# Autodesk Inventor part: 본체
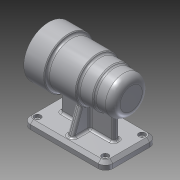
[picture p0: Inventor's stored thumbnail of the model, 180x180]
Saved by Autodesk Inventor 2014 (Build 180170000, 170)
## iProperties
Created: 2016-06
Part Number: 본체
Material: Aluminum 6061
Document SubType Name: Modeling
Designer: user
Density: 2.71 g/cm^3
Appearance: Aluminum - Flat
Mass: 673.031 g
Surface Area: 650.376 cm^2
Volume: 248.351 cm^3
Author: user
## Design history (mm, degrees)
sketch "Sketch1"
  geometry: L1 (-56, 35)-(56, 35); L2 (56, 35)-(56, -35); L3 (56, -35)-(-56, -35); L4 (-56, -35)-(-56, 35); 3 further points
  constraints: 8 end point, 2 midpoint, 2 parallel, 1 horizontal, 1 horizontal alignment, 1 perpendicular, 1 vertical alignment
  dimensions: "d0" = 112 distance of L2.end L3.end; "d1" = 70 distance of L1.end L2.end
extrude "Extrusion1" new body sketch "Sketch1" distance "d2" = 10; taper "d3" = 0 deg
fillet "Fillet1" dims "d4" = 10
workplane "Work Plane1"
sketch "Sketch2"
  geometry: L1 (25, 0)-(-25, 0) reference; C1 r 25 at (0, 70); 1 further point
  constraints: 1 centre point
  dimensions: "d6" = 50 diameter of C1; "d7" = 70 distance from line of L1 C1.centre
extrude "Extrusion2" join sketch "Sketch2" distance "d8" = 25; taper "d9" = 0 deg
sketch "Sketch3"
  geometry: C1 r 25 at (0, 0) reference; C2 r 27 at (0, 0); 1 further point
  constraints: 1 centre point, 1 coincident
  dimensions: "d10" = 54 diameter of C2
extrude "Extrusion3" join sketch "Sketch3" distance "d11" = 20; taper "d12" = 0 deg
sketch "Sketch4"
  geometry: C1 r 27 at (0, 0) reference; C2 r 30 at (0, 0); 1 further point
  constraints: 1 centre point, 1 coincident
  dimensions: "d13" = 60 diameter of C2
extrude "Extrusion4" join sketch "Sketch4" distance "d14" = 39; taper "d15" = 0 deg
sketch "Sketch5"
  geometry: C1 r 30 at (0, 0) reference; C2 r 34 at (0, 0); 1 further point
  constraints: 1 centre point, 1 coincident
  dimensions: "d16" = 68 diameter of C2
extrude "Extrusion5" join sketch "Sketch5" distance "d17" = 28; taper "d18" = 0 deg
workplane "Work Plane2"
sketch "Sketch6"
  geometry: L1 (36, -4)-(-36, -4); L2 (-36, -4)-(-36, 4); L3 (-36, 4)-(36, 4); L4 (36, 4)-(36, -4); 3 further points
  constraints: 8 end point, 2 midpoint, 2 parallel, 1 horizontal, 1 horizontal alignment, 1 perpendicular, 1 vertical alignment
  dimensions: "d20" = 8 distance of L1.end L2.end; "d21" = 72 distance of L1.start L1.end
extrude "Extrusion6" join sketch "Sketch6" stored distance "d22" = 28; taper "d23" = 0 deg
chamfer "Chamfer1" distance "d24" = 4; stored, may be unused: second distance "d25" = 2, angle "d26" = 45 deg
sketch "Sketch7"
  geometry: C1 r 34 at (0, 0) reference; C2 r 21 at (0, 0); 1 further point
  constraints: 1 centre point, 1 coincident
  dimensions: "d27" = 42 diameter of C2
extrude "Extrusion7" cut sketch "Sketch7" distance "d28" = 15; taper "d29" = 0 deg
sketch "Sketch8"
  geometry: C1 r 21 at (0, 0) reference; C2 r 24 at (0, 0); 1 further point
  constraints: 1 centre point, 1 coincident
  dimensions: "d30" = 48 diameter of C2
extrude "Extrusion8" cut sketch "Sketch8" distance "d31" = 54; taper "d32" = 0 deg
sketch "Sketch9"
  geometry: C1 r 24 at (0, 0) reference; C2 r 21 at (0, 0); 1 further point
  constraints: 1 centre point, 1 coincident
  dimensions: "d33" = 42 diameter of C2
extrude "Extrusion9" cut sketch "Sketch9" distance "d34" = 12; taper "d35" = 0 deg
sketch "Sketch10"
  geometry: C1 r 21 at (0, 0) reference; C2 r 17.5 at (0, 0); 1 further point
  constraints: 1 centre point, 1 coincident
  dimensions: "d36" = 35 diameter of C2
extrude "Extrusion10" cut sketch "Sketch10" distance "d37" = 18; taper "d38" = 0 deg
sketch "Sketch11"
  geometry: C1 r 17.5 at (0, 0) reference; C2 r 16 at (0, 0); 1 further point
  constraints: 1 centre point, 1 coincident
  dimensions: "d39" = 32 diameter of C2
extrude "Extrusion11" cut sketch "Sketch11" distance "d40" = 4; taper "d41" = 0 deg
sketch "Sketch12"
  geometry: C1 r 16 at (0, 0) reference; C2 r 10.5 at (0, 0); 1 further point
  constraints: 1 centre point, 1 coincident
  dimensions: "d42" = 21 diameter of C2
extrude "Extrusion12" cut sketch "Sketch12" distance "d43" = 3; taper "d44" = 0 deg
fillet "Fillet2" dims "d45" = 10
fillet "Fillet3" dims "d46" = 3
fillet "Fillet4" dims "d47" = 0.3
fillet "Fillet5" dims "d48" = 3
chamfer "Chamfer2" distance "d49" = 1; stored, may be unused: second distance "d50" = 2, angle "d51" = 45 deg
sketch "Sketch13"
  geometry: C1 r 34 at (0, 0) reference; 2 further points
  dimensions: "d52" = 26 distance of C1.centre point (26, 0)
hole "Hole1" sketch "Sketch13" at (26, 0) diameter "d53" = 3.242; stored, may be unused: countersink angle "d57" = 90 deg, drill point angle "d59" = 118 deg; dims "d54" = 8, "d55" = 4, "d56" = 2, "d58" = 11
pattern_circular "Circular Pattern1" dims angle "d61" = 360 deg
sketch "Sketch14"
  geometry: L1 (56, -25)-(56, 25) reference; 3 further points
  dimensions: "d63" = 50 distance of point (46, 24.728) point (46, -25.272); "d64" = 10 distance from line of point (46, -25.272) L1; "d65" = 10 distance from line of L1 point (46, 24.728)
hole "Hole2" sketch "Sketch14" at (46, -25.272), (46, 24.728) diameter "d66" = 5; stored, may be unused: countersink angle "d70" = 90 deg, drill point angle "d72" = 0 deg; dims "d67" = 8, "d68" = 9, "d69" = 4, "d71" = 10
mirror "Mirror1"
sketch "Sketch15"
  geometry: L1 (15.509, 44.32)-(28, 10); L2 (-25, 10)-(25, 10) reference; L3 (25, 10)-(31, 10) reference; A1 r 30 centre (0, 70) between (4, 40.268) and (-4, 40.268) reference; A2 r 30 centre (0, 70) between (4, 40.268) and (-4, 40.268) reference; A3 r 30 centre (0, 70) between (4, 40.268) and (-4, 40.268) reference; 2 further points
  constraints: 2 end point, 2 point on circle, 1 point on line
  dimensions: "d73" = 7 horizontal distance of point (35, 0) L1.end; "d74" = 110 deg angle of L3 L1
feature "Rib1" sketch "Sketch15" dims "d75" = 8, "d76" = 8, "d77" = 0, "d78" = 0, "d79" = 1, "d80" = 1
mirror "Mirror2"
fillet "Fillet6" dims "d81" = 3
workplane "Work Plane3"
sketch "Sketch16"
  geometry: L1 (-7.909, 72.251)-(23.909, 72.251); L2 (23.909, 72.251)-(23.909, 67.749); L3 (23.909, 67.749)-(-7.909, 67.749); L4 (-7.909, 67.749)-(-7.909, 72.251); L5 (46, 0)-(-46, 0) reference; L6 (56, 36)-(56, 104) reference; 4 further points
  constraints: 2 midpoint, 1 horizontal alignment, 1 vertical alignment, 2 other
  dimensions: "d87" = 70 distance from line of L5 point (8, 70); "d88" = 48 distance from line of L6 point (8, 70)
emboss "Emboss1" sketch "Sketch16" dims "d89" = 0.5, "d90" = 0
fillet "Fillet8" dims "d91" = 3
fillet "Fillet9" dims "d92" = 3
chamfer "Chamfer5" distance "d96" = 1; stored, may be unused: second distance "d97" = 2, angle "d98" = 45 deg
body "Solid1"
node "Projected Loop1"
other parameters: "d5" = 56, "d19" = -56
